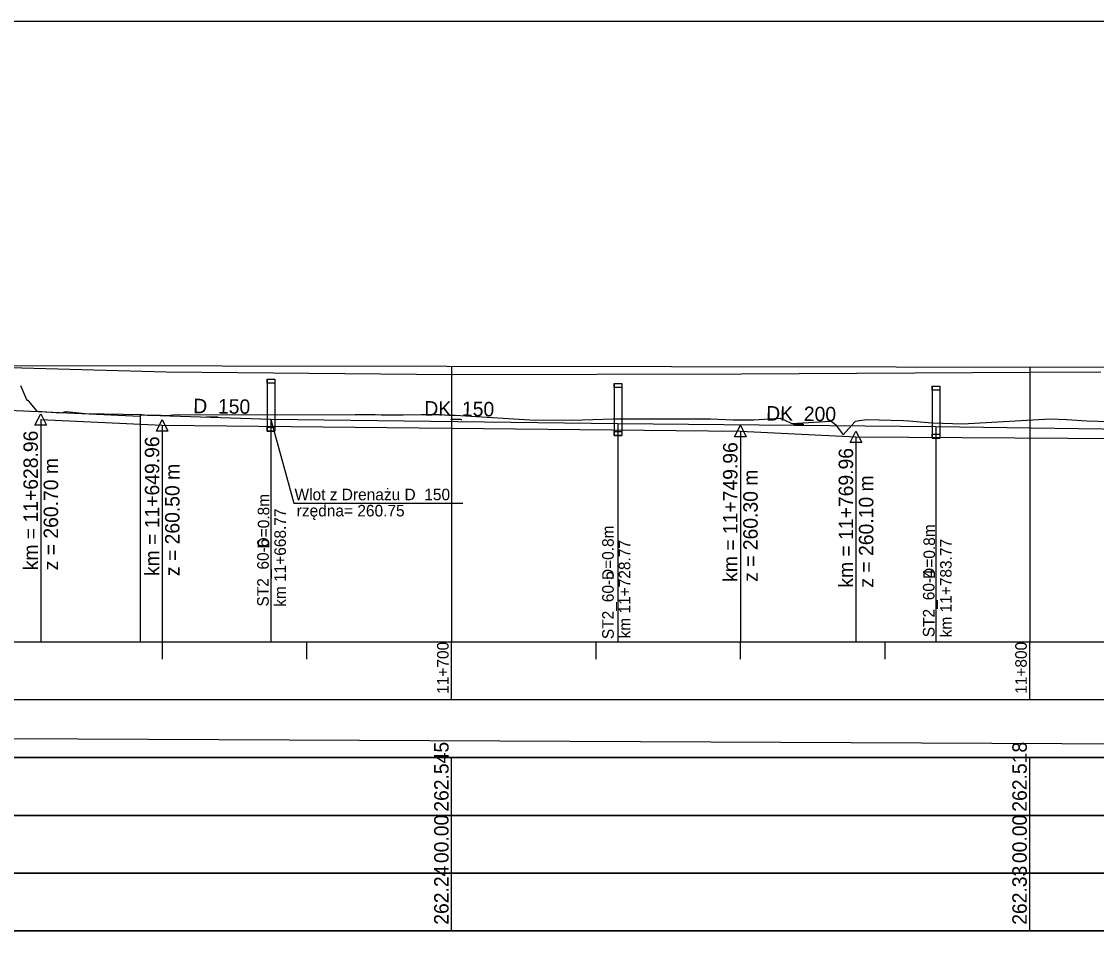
# Model space of a CAD drawing. Extents: x 6445630 to 6518227, y 5499240 to 5511716.
# Drawn here: x 6453656.8 to 6453842.8, y 5508188.4 to 5508348.6 of the extents above; entities that cross this region are included whole.
import ezdxf

# ---------------------------------------------------------------- set-up
doc = ezdxf.new("R2010")
doc.units = 0
for name, color, linetype in [('TOR_PROF-drenaze', 7, 'Continuous'), ('TOR_PROF-drenokolektory', 7, 'Continuous'), ('TOR_PROF-obiekty+opisy', 7, 'Continuous'), ('TOR_PROF-opisy glowne', 7, 'Continuous'), ('TOR_PROF-opisy pomocnicze', 7, 'Continuous'), ('TOR_PROF-rowy otwarte', 7, 'Continuous'), ('TOR_PROF-studnie i osadniki', 7, 'Continuous'), ('TOR_PROF-tabelka-odleglosci T1', 7, 'Continuous'), ('TOR_PROF-tabelka-pochylenia proj T1', 7, 'Continuous'), ('TOR_PROF-tabelka-rzedne istn T1', 7, 'Continuous'), ('TOR_PROF-tabelka-rzedne proj T1', 7, 'Continuous'), ('TOR_PROF-tabelka-teren istniejacy T1', 7, 'Continuous'), ('TOR_PROF-tor istniejacy T2', 7, 'Continuous'), ('TOR_PROF-tor projektowany', 7, 'Continuous'), ('TOR_PROF-uklad odniesienia', 7, 'Continuous'), ('TOR_RAMKI-dodatkowe3', 7, 'Continuous'), ('TOR_RAMKI-MASKA WYCIECIA', 7, 'Continuous')]:
    doc.layers.add(name, color=color, linetype=linetype)

msp = doc.modelspace()

# ---------------------------------------------------------------- linework, layer by layer
at = {"layer": 'TOR_PROF-drenaze'}
for points in [[(6453677.38, 5508280.29), (6453644.48, 5508281.79)], [(6453699.98, 5508279.79), (6453677.38, 5508280.54)], [(6453759.98, 5508279.04), (6453699.98, 5508279.79)]]:
    msp.add_lwpolyline(points, dxfattribs=at)
at = {"layer": 'TOR_PROF-drenokolektory'}
for points in [[(6453677.38, 5508280.54), (6453677.38, 5508246.29), (6453677.38, 5508241.29), (6453677.38, 5508241.29)], [(6453677.38, 5508280.29), (6453677.38, 5508246.29), (6453677.38, 5508241.29), (6453677.38, 5508241.29)], [(6453677.38, 5508280.29), (6453677.38, 5508246.29), (6453677.38, 5508241.29), (6453677.38, 5508241.29)], [(6453677.38, 5508280.29), (6453677.38, 5508246.29), (6453677.38, 5508241.29), (6453677.38, 5508241.29)], [(6453699.98, 5508279.79), (6453699.98, 5508246.29), (6453699.98, 5508241.29), (6453699.98, 5508241.29)], [(6453699.98, 5508279.79), (6453699.98, 5508246.29), (6453699.98, 5508241.29), (6453699.98, 5508241.29)], [(6453699.98, 5508279.79), (6453699.98, 5508246.29), (6453699.98, 5508241.29), (6453699.98, 5508241.29)], [(6453699.98, 5508279.79), (6453699.98, 5508246.29), (6453699.98, 5508241.29), (6453699.98, 5508241.29)], [(6453814.98, 5508278.54), (6453759.98, 5508279.04)], [(6453759.98, 5508279.04), (6453759.98, 5508246.29), (6453759.98, 5508241.29), (6453759.98, 5508241.29)], [(6453759.98, 5508279.04), (6453759.98, 5508246.29), (6453759.98, 5508241.29), (6453759.98, 5508241.29)], [(6453759.98, 5508279.04), (6453759.98, 5508246.29), (6453759.98, 5508241.29), (6453759.98, 5508241.29)], [(6453759.98, 5508279.04), (6453759.98, 5508246.29), (6453759.98, 5508241.29), (6453759.98, 5508241.29)], [(6453884.99, 5508277.54), (6453814.98, 5508278.54)], [(6453814.98, 5508278.54), (6453814.98, 5508246.29), (6453814.98, 5508241.29), (6453814.98, 5508241.29)], [(6453814.98, 5508278.54), (6453814.98, 5508246.29), (6453814.98, 5508241.29), (6453814.98, 5508241.29)], [(6453814.98, 5508278.54), (6453814.98, 5508246.29), (6453814.98, 5508241.29), (6453814.98, 5508241.29)], [(6453814.98, 5508278.54), (6453814.98, 5508246.29), (6453814.98, 5508241.29), (6453814.98, 5508241.29)]]:
    msp.add_lwpolyline(points, dxfattribs=at)
at = {"layer": 'TOR_PROF-obiekty+opisy'}
for p, q in [((6453699.98, 5508279.79), (6453703.91, 5508265.3)), ((6453703.91, 5508265.3), (6453733.15, 5508265.3))]:
    msp.add_line(p, q, dxfattribs=at)
at = {"layer": 'TOR_PROF-opisy pomocnicze'}
for p, q in [((6453660.17, 5508279.79), (6453660.17, 5508252.79)), ((6453681.17, 5508278.79), (6453681.17, 5508251.79)), ((6453781.17, 5508277.79), (6453781.17, 5508250.79)), ((6453801.17, 5508276.79), (6453801.17, 5508249.79))]:
    msp.add_line(p, q, dxfattribs=at)
for points in [[(6453660.17, 5508280.79), (6453661.17, 5508278.79), (6453659.17, 5508278.79)], [(6453681.17, 5508279.79), (6453682.17, 5508277.79), (6453680.17, 5508277.79)], [(6453781.17, 5508278.79), (6453782.17, 5508276.79), (6453780.17, 5508276.79)], [(6453801.17, 5508277.79), (6453802.17, 5508275.79), (6453800.17, 5508275.79)]]:
    msp.add_lwpolyline(points, close=True, dxfattribs=at)
at = {"layer": 'TOR_PROF-rowy otwarte'}
for p, q in [((6453660.17, 5508279.79), (6453681.17, 5508278.79)), ((6453681.17, 5508278.79), (6453781.17, 5508277.79)), ((6453781.17, 5508277.79), (6453801.17, 5508276.79)), ((6453801.17, 5508276.79), (6453926.17, 5508276.04))]:
    msp.add_line(p, q, dxfattribs=at)
for points in [[(6453660.17, 5508279.79), (6453660.17, 5508246.29), (6453660.17, 5508241.29), (6453660.17, 5508241.29)], [(6453681.17, 5508278.79), (6453681.17, 5508246.29), (6453681.17, 5508241.29), (6453681.17, 5508241.29)], [(6453781.17, 5508277.79), (6453781.17, 5508246.29), (6453781.17, 5508241.29), (6453781.17, 5508241.29)], [(6453801.17, 5508276.79), (6453801.17, 5508246.29), (6453801.17, 5508241.29), (6453801.17, 5508241.29)]]:
    msp.add_lwpolyline(points, dxfattribs=at)
at = {"layer": 'TOR_PROF-studnie i osadniki'}
for p, q in [((6453699.35, 5508286.78), (6453699.35, 5508277.78)), ((6453699.35, 5508286.78), (6453700.65, 5508286.78)), ((6453700.65, 5508286.78), (6453700.65, 5508277.78)), ((6453759.35, 5508286.03), (6453759.35, 5508277.03)), ((6453759.35, 5508286.03), (6453760.65, 5508286.03)), ((6453760.65, 5508286.03), (6453760.65, 5508277.03)), ((6453814.35, 5508285.53), (6453814.35, 5508276.53)), ((6453814.35, 5508285.53), (6453815.65, 5508285.53)), ((6453815.65, 5508285.53), (6453815.65, 5508276.53)), ((6453699.35, 5508277.78), (6453700.65, 5508277.78)), ((6453759.35, 5508277.03), (6453760.65, 5508277.03)), ((6453814.35, 5508276.53), (6453815.65, 5508276.53))]:
    msp.add_line(p, q, dxfattribs=at)
for points in [[(6453699.35, 5508286.78), (6453700.65, 5508286.78), (6453700.65, 5508286.08), (6453699.35, 5508286.08)], [(6453759.35, 5508286.03), (6453760.65, 5508286.03), (6453760.65, 5508285.33), (6453759.35, 5508285.33)], [(6453814.35, 5508285.53), (6453815.65, 5508285.53), (6453815.65, 5508284.83), (6453814.35, 5508284.83)], [(6453699.35, 5508278.48), (6453700.65, 5508278.48), (6453700.65, 5508277.78), (6453699.35, 5508277.78)], [(6453759.35, 5508277.73), (6453760.65, 5508277.73), (6453760.65, 5508277.03), (6453759.35, 5508277.03)], [(6453814.35, 5508277.23), (6453815.65, 5508277.23), (6453815.65, 5508276.53), (6453814.35, 5508276.53)]]:
    msp.add_lwpolyline(points, close=True, dxfattribs=at)
at = {"layer": 'TOR_PROF-tabelka-odleglosci T1'}
msp.add_lwpolyline([(6452331.21, 5508201.29), (6454631.21, 5508201.29), (6454631.21, 5508211.29), (6452331.21, 5508211.29)], close=True, dxfattribs=at)
for points in [[(6453731.21, 5508201.29), (6453731.21, 5508211.29)], [(6453831.21, 5508201.29), (6453831.21, 5508211.29)]]:
    msp.add_lwpolyline(points, dxfattribs=at)
at = {"layer": 'TOR_PROF-tabelka-pochylenia proj T1'}
msp.add_lwpolyline([(6452331.21, 5508221.29), (6454631.21, 5508221.29), (6454631.21, 5508231.29), (6452331.21, 5508231.29)], close=True, dxfattribs=at)
msp.add_lwpolyline([(6452560.71, 5508229.79), (6454031.21, 5508222.79)], dxfattribs=at)
at = {"layer": 'TOR_PROF-tabelka-rzedne istn T1'}
msp.add_lwpolyline([(6452331.21, 5508191.29), (6454631.21, 5508191.29), (6454631.21, 5508201.29), (6452331.21, 5508201.29)], close=True, dxfattribs=at)
for points in [[(6453731.21, 5508191.29), (6453731.21, 5508201.29)], [(6453831.21, 5508191.29), (6453831.21, 5508201.29)]]:
    msp.add_lwpolyline(points, dxfattribs=at)
at = {"layer": 'TOR_PROF-tabelka-rzedne proj T1'}
msp.add_lwpolyline([(6452331.21, 5508211.29), (6454631.21, 5508211.29), (6454631.21, 5508221.29), (6452331.21, 5508221.29)], close=True, dxfattribs=at)
for points in [[(6453731.21, 5508211.29), (6453731.21, 5508221.29)], [(6453831.21, 5508211.29), (6453831.21, 5508221.29)]]:
    msp.add_lwpolyline(points, dxfattribs=at)
at = {"layer": 'TOR_PROF-tabelka-teren istniejacy T1'}
msp.add_lwpolyline([(6452331.21, 5508181.29), (6454631.21, 5508181.29), (6454631.21, 5508191.29), (6452331.21, 5508191.29)], close=True, dxfattribs=at)
at = {"layer": 'TOR_PROF-tor istniejacy T2'}
msp.add_lwpolyline([(6453843.51, 5508287.99), (6453831.36, 5508287.94), (6453781.3, 5508287.64), (6453731.31, 5508287.49), (6453681.83, 5508287.99), (6453631.88, 5508289.34)], dxfattribs=at)
at = {"layer": 'TOR_PROF-tor projektowany'}
msp.add_line((6452560.71, 5508290.59), (6454031.21, 5508288.61), dxfattribs=at)
msp.add_line((6452560.71, 5508290.59), (6454031.21, 5508288.61), dxfattribs=at)
for points in [[(6453731.21, 5508289.01), (6453731.21, 5508246.29), (6453731.21, 5508241.29), (6453731.21, 5508241.29)], [(6453731.21, 5508289.01), (6453731.21, 5508246.29), (6453731.21, 5508241.29), (6453731.21, 5508241.29)], [(6453731.21, 5508289.01), (6453731.21, 5508246.29), (6453731.21, 5508241.29), (6453731.21, 5508241.29)], [(6453731.21, 5508289.01), (6453731.21, 5508246.29), (6453731.21, 5508241.29), (6453731.21, 5508241.29)], [(6453731.21, 5508289.01), (6453731.21, 5508246.29), (6453731.21, 5508241.29), (6453731.21, 5508241.29)], [(6453731.21, 5508289.01), (6453731.21, 5508246.29), (6453731.21, 5508241.29), (6453731.21, 5508241.29)], [(6453831.21, 5508288.88), (6453831.21, 5508246.29), (6453831.21, 5508241.29), (6453831.21, 5508241.29)], [(6453831.21, 5508288.88), (6453831.21, 5508246.29), (6453831.21, 5508241.29), (6453831.21, 5508241.29)], [(6453831.21, 5508288.88), (6453831.21, 5508246.29), (6453831.21, 5508241.29), (6453831.21, 5508241.29)], [(6453831.21, 5508288.88), (6453831.21, 5508246.29), (6453831.21, 5508241.29), (6453831.21, 5508241.29)], [(6453831.21, 5508288.88), (6453831.21, 5508246.29), (6453831.21, 5508241.29), (6453831.21, 5508241.29)], [(6453831.21, 5508288.88), (6453831.21, 5508246.29), (6453831.21, 5508241.29), (6453831.21, 5508241.29)]]:
    msp.add_lwpolyline(points, dxfattribs=at)
at = {"layer": 'TOR_PROF-uklad odniesienia'}
for p, q in [((6452331.21, 5508241.29), (6454631.21, 5508241.29)), ((6453681.21, 5508238.29), (6453681.21, 5508241.29)), ((6453681.21, 5508238.29), (6453681.21, 5508241.29)), ((6453706.21, 5508238.29), (6453706.21, 5508241.29)), ((6453706.21, 5508238.29), (6453706.21, 5508241.29)), ((6453731.21, 5508231.29), (6453731.21, 5508241.29)), ((6453731.21, 5508231.29), (6453731.21, 5508241.29)), ((6453756.21, 5508238.29), (6453756.21, 5508241.29)), ((6453756.21, 5508238.29), (6453756.21, 5508241.29)), ((6453781.21, 5508238.29), (6453781.21, 5508241.29)), ((6453781.21, 5508238.29), (6453781.21, 5508241.29)), ((6453806.21, 5508238.29), (6453806.21, 5508241.29)), ((6453806.21, 5508238.29), (6453806.21, 5508241.29)), ((6453831.21, 5508231.29), (6453831.21, 5508241.29)), ((6453831.21, 5508231.29), (6453831.21, 5508241.29))]:
    msp.add_line(p, q, dxfattribs=at)
at = {"layer": 'TOR_RAMKI-dodatkowe3'}
for p, q in [((6453656.68, 5508285.68), (6453657.7, 5508283.23)), ((6453657.7, 5508283.23), (6453657.74, 5508283.13)), ((6453657.74, 5508283.13), (6453657.93, 5508283.1)), ((6453657.93, 5508283.1), (6453658.3, 5508282.66)), ((6453658.3, 5508282.66), (6453659.5, 5508281.22)), ((6453659.5, 5508281.22), (6453663.68, 5508280.95)), ((6453663.68, 5508280.95), (6453664.54, 5508281.17)), ((6453664.54, 5508281.17), (6453667.84, 5508280.81)), ((6453667.84, 5508280.81), (6453677.64, 5508280.65)), ((6453677.64, 5508280.65), (6453678.62, 5508280.54)), ((6453678.62, 5508280.54), (6453681.01, 5508280.53)), ((6453681.01, 5508280.53), (6453681.84, 5508280.48)), ((6453681.84, 5508280.48), (6453683.04, 5508280.6)), ((6453683.04, 5508280.6), (6453714.53, 5508280.62)), ((6453714.53, 5508280.62), (6453718.02, 5508280.62)), ((6453718.02, 5508280.62), (6453719.06, 5508280.58)), ((6453719.06, 5508280.58), (6453722.87, 5508280.58)), ((6453722.87, 5508280.58), (6453726.02, 5508280.62)), ((6453726.02, 5508280.62), (6453729.14, 5508280.62)), ((6453729.14, 5508280.62), (6453730.84, 5508280.55)), ((6453730.84, 5508280.55), (6453731.84, 5508280.54)), ((6453731.84, 5508280.54), (6453745.7, 5508279.66)), ((6453745.7, 5508279.66), (6453749, 5508279.7)), ((6453749, 5508279.7), (6453752.09, 5508279.67)), ((6453752.09, 5508279.67), (6453755.67, 5508279.77)), ((6453755.67, 5508279.77), (6453759.15, 5508279.89)), ((6453759.15, 5508279.89), (6453775.98, 5508279.89)), ((6453775.98, 5508279.89), (6453779.95, 5508279.72)), ((6453779.95, 5508279.72), (6453783.48, 5508279.7)), ((6453783.48, 5508279.7), (6453788.07, 5508280.03)), ((6453788.07, 5508280.03), (6453788.86, 5508279.64)), ((6453788.86, 5508279.64), (6453790.08, 5508279.06)), ((6453790.08, 5508279.06), (6453796.75, 5508279.51)), ((6453796.75, 5508279.51), (6453797.13, 5508279.33)), ((6453797.13, 5508279.33), (6453797.64, 5508278.89)), ((6453797.64, 5508278.89), (6453798.95, 5508277.13)), ((6453798.95, 5508277.13), (6453800.99, 5508279.38)), ((6453800.99, 5508279.38), (6453801.1, 5508279.48)), ((6453801.1, 5508279.48), (6453801.44, 5508279.54)), ((6453801.44, 5508279.54), (6453801.7, 5508279.58)), ((6453801.7, 5508279.58), (6453801.76, 5508279.59)), ((6453801.76, 5508279.59), (6453803.02, 5508279.78)), ((6453803.02, 5508279.78), (6453809.39, 5508279.59)), ((6453809.39, 5508279.59), (6453810.33, 5508279.54)), ((6453810.33, 5508279.54), (6453814.36, 5508279.2)), ((6453814.36, 5508279.2), (6453819.67, 5508279.02)), ((6453819.67, 5508279.02), (6453834.73, 5508279.88)), ((6453834.73, 5508279.88), (6453837.63, 5508279.8)), ((6453837.63, 5508279.8), (6453841.1, 5508279.56)), ((6453841.1, 5508279.56), (6453847.16, 5508279.38))]:
    msp.add_line(p, q, dxfattribs=at)
at = {"layer": 'TOR_RAMKI-MASKA WYCIECIA'}
msp.add_lwpolyline([(6452261.34, 5508061.65), (6454661.34, 5508061.65), (6454661.34, 5508348.65), (6452261.34, 5508348.65)], close=True, dxfattribs=at)

# ---------------------------------------------------------------- texts
at = {"layer": 'TOR_PROF-drenaze'}
for s, p in [('D_150', (6453686.53, 5508280.88)), ('DK_150', (6453726.5, 5508280.47)), ('DK_200', (6453785.63, 5508279.61))]:
    msp.add_text(s, height=2.5, rotation=359.2555, dxfattribs=at).set_placement(p)
at = {"layer": 'TOR_PROF-opisy glowne'}
for s, p in [('D=0.8m', (6453699.7, 5508257.46)), ('km 11+668.77', (6453702.57, 5508247.36)), ('D=0.8m', (6453759.27, 5508252)), ('D=0.8m', (6453814.84, 5508252.2)), ('ST2_60-6', (6453699.6, 5508247.42)), ('km 11+728.77', (6453762.14, 5508241.9)), ('km 11+783.77', (6453817.72, 5508242.09)), ('ST2_60-5', (6453759.27, 5508241.78)), ('ST2_60-4', (6453814.75, 5508242.11))]:
    msp.add_text(s, height=2, rotation=90, dxfattribs=at).set_placement(p)
at = {"layer": 'TOR_PROF-opisy pomocnicze'}
for s, p in [('km = 11+628.96', (6453659.67, 5508253.69)), ('km = 11+649.96', (6453680.67, 5508252.69)), ('km = 11+749.96', (6453780.67, 5508251.69)), ('km = 11+769.96', (6453800.67, 5508250.69)), ('z = 260.70 m', (6453663.17, 5508253.69)), ('z = 260.50 m', (6453684.17, 5508252.69)), ('z = 260.30 m', (6453784.17, 5508251.69)), ('z = 260.10 m', (6453804.17, 5508250.69))]:
    msp.add_text(s, height=2.5, rotation=90, dxfattribs=at).set_placement(p)
for s, p in [('Wlot z Drenażu D_150 ', (6453704.06, 5508265.81)), ('rzędna= 260.75 ', (6453704.44, 5508263.01))]:
    msp.add_text(s, height=2, dxfattribs=at).set_placement(p)
at = {"layer": 'TOR_PROF-tabelka-odleglosci T1'}
for p in [(6453730.71, 5508203.03), (6453830.71, 5508203.03)]:
    msp.add_text('00.00', height=2.5, rotation=90, dxfattribs=at).set_placement(p)
at = {"layer": 'TOR_PROF-tabelka-rzedne istn T1'}
for s, p in [('262.24', (6453730.71, 5508192.36)), ('262.33', (6453830.71, 5508192.35))]:
    msp.add_text(s, height=2.5, rotation=90, dxfattribs=at).set_placement(p)
at = {"layer": 'TOR_PROF-tabelka-rzedne proj T1'}
for s, p in [('262.545', (6453730.71, 5508211.92)), ('262.518', (6453830.71, 5508211.92))]:
    msp.add_text(s, height=2.5, rotation=90, dxfattribs=at).set_placement(p)
at = {"layer": 'TOR_PROF-uklad odniesienia'}
for s, p in [('11+700', (6453730.71, 5508232.31)), ('11+700', (6453730.71, 5508232.31)), ('11+800', (6453830.71, 5508232.31)), ('11+800', (6453830.71, 5508232.31))]:
    msp.add_text(s, height=2, rotation=90, dxfattribs=at).set_placement(p)

doc.saveas('drawing.dxf')
